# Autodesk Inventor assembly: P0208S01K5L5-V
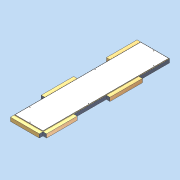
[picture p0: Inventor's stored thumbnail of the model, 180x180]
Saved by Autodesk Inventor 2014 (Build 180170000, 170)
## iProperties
Created: 2011-04
Part Number: P0208S01K5L5-V
Document SubType Name: Assembly
Designer: david.appleford
Description: 0.5w x 2w 01 Panel - 5 Locks 5 Lugs
Mass: 29000 g
Surface Area: 38756.7 cm^2
Volume: 115596 cm^3
Density: 0.250874 g/cm^3
Cost Center: £113.00
Justset: False
Title: 0.5w x 2w 01 Panel - 5 Locks 5 Lugs
Author: david.appleford
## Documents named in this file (5)
- C:\Documents and Settings\john.everitt\Local Settings\My Documents\Vault\Production MkII\VIRTUAL ELEMENTS\Virtual Walls\Virtual Timber + MgO\P0208S01K5L5-V.iam
- C:\Documents and Settings\john.everitt\Local Settings\My Documents\Vault\Production MkII\VIRTUAL ELEMENTS\Virtual Walls\Virtual Timber + MgO\P0208S01K6-V.ipt
- C:\Documents and Settings\john.everitt\Local Settings\My Documents\Vault\Production MkII\VIRTUAL ELEMENTS\Virtual Lugs\LA02C3CC-V.ipt
- C:\Documents and Settings\john.everitt\Local Settings\My Documents\Vault\Production MkII\VIRTUAL ELEMENTS\Virtual Lugs\LA02M3CC-V.ipt
- C:\Documents and Settings\john.everitt\Local Settings\My Documents\Vault\Production MkII\VIRTUAL ELEMENTS\Virtual Lugs\LA02E3CC-V.ipt
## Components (6 placed, 4 different names)
1. P0208S01K6-V:1 — Mate:1, Flush:1, Flush:2, Mate:5, Mate:6, Flush:9, Flush:10, Mate:7, Flush:11, Mate:14, Flush:12, Flush:13
2. LA02C3CC-V:1 — Mate:1, Flush:1, Flush:2, Mate:9, Mate:13
3. LA02C3CC-V:2 — Mate:6, Flush:9, Mate:12
4. LA02M3CC-V:1 — Mate:5, Flush:10, Mate:12, Mate:13
5. LA02M3CC-V:2 — Mate:7, Flush:11, Mate:9
6. LA02E3CC-V:1 — Mate:14, Flush:12, Flush:13
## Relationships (15: Mate 8, Flush 7)
- Mate:1: P0208S01K6-V:1 ↔ LA02C3CC-V:1
- Flush:1: P0208S01K6-V:1 ↔ LA02C3CC-V:1
- Flush:2: P0208S01K6-V:1 ↔ LA02C3CC-V:1
- Mate:5: P0208S01K6-V:1 ↔ LA02M3CC-V:1
- Mate:6: P0208S01K6-V:1 ↔ LA02C3CC-V:2
- Flush:9: P0208S01K6-V:1 ↔ LA02C3CC-V:2
- Flush:10: P0208S01K6-V:1 ↔ LA02M3CC-V:1
- Mate:7: P0208S01K6-V:1 ↔ LA02M3CC-V:2
- Flush:11: P0208S01K6-V:1 ↔ LA02M3CC-V:2
- Mate:9: LA02C3CC-V:1 ↔ LA02M3CC-V:2
- Mate:12: LA02C3CC-V:2 ↔ LA02M3CC-V:1
- Mate:13: LA02C3CC-V:1 ↔ LA02M3CC-V:1
- Mate:14: P0208S01K6-V:1 ↔ LA02E3CC-V:1
- Flush:12: P0208S01K6-V:1 ↔ LA02E3CC-V:1
- Flush:13: P0208S01K6-V:1 ↔ LA02E3CC-V:1
## Named parameters: t = 1 mm, Cl = 2 mm
